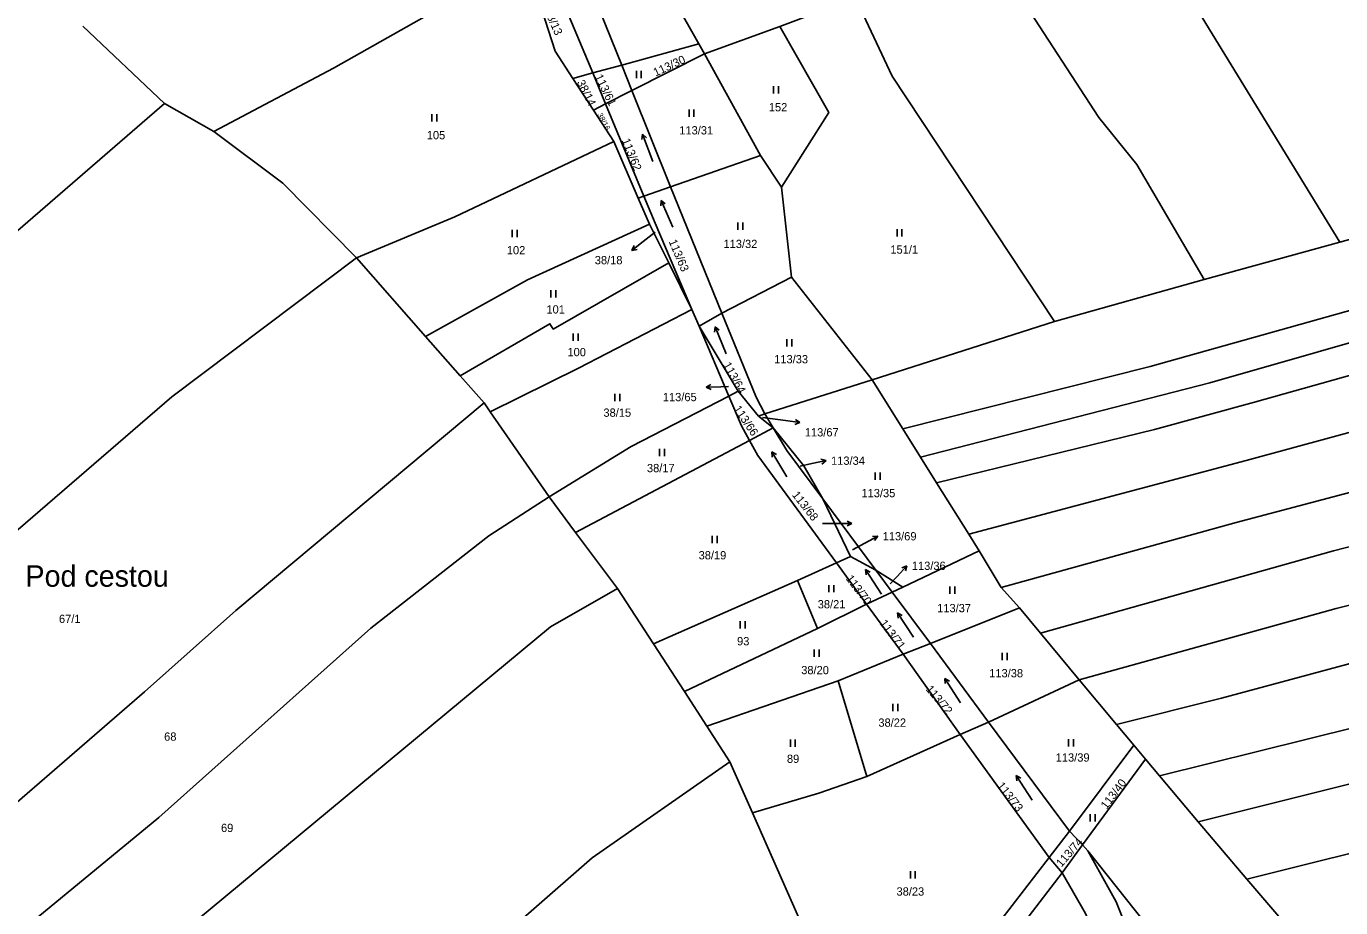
# Model space of a CAD drawing. Extents: x -751333 to -746055, y -1133395 to -1129777.
# Drawn here: x -747546.5 to -747276.5, y -1131322.6 to -1131141.4 of the extents above; entities that cross this region are included whole.
import ezdxf

# ---------------------------------------------------------------- set-up
doc = ezdxf.new("R2010")
doc.units = 0
for name, color, linetype in [('Hranice parcel', 7, 'Continuous'), ('Parcelní čísla', 7, 'Continuous'), ('Pop  PČ popisy', 7, 'Continuous'), ('Značky kultur', 7, 'Continuous')]:
    doc.layers.add(name, color=color, linetype=linetype)

msp = doc.modelspace()

# ---------------------------------------------------------------- linework, layer by layer
at = {"layer": 'Hranice parcel'}
for p, q in [((-747408.38, -1131145.07), (-747431.95, -1131103.02)), ((-747440.84, -1131108.03), (-747424.22, -1131149.41)), ((-747430.18, -1131151.04), (-747446.81, -1131111.05)), ((-747376.22, -1131135.6), (-747391.74, -1131141.48)), ((-747518.15, -1131157.34), (-747534.94, -1131141.41)), ((-747407.22, -1131147.14), (-747391.74, -1131141.48)), ((-747424.22, -1131149.41), (-747408.38, -1131145.07)), ((-747407.22, -1131147.14), (-747408.38, -1131145.07)), ((-747422.11, -1131154.66), (-747407.22, -1131147.14)), ((-747395.7, -1131168), (-747407.22, -1131147.14)), ((-747430.18, -1131151.04), (-747424.22, -1131149.41)), ((-747424.22, -1131149.41), (-747422.11, -1131154.66)), ((-747434.26, -1131152.16), (-747430.18, -1131151.04)), ((-747434.26, -1131152.16), (-747430.03, -1131158.67)), ((-747427.53, -1131157.41), (-747430.18, -1131151.04)), ((-747427.53, -1131157.41), (-747422.11, -1131154.66)), ((-747422.11, -1131154.66), (-747414.16, -1131174.44)), ((-747508, -1131163.09), (-747518.15, -1131157.34)), ((-747430.03, -1131158.67), (-747427.53, -1131157.41)), ((-747430.03, -1131158.67), (-747425.84, -1131165.11)), ((-747419.66, -1131176.34), (-747427.53, -1131157.41)), ((-747425.84, -1131165.11), (-747420.83, -1131176.75)), ((-747414.16, -1131174.44), (-747395.7, -1131168)), ((-747391.42, -1131174.47), (-747395.7, -1131168)), ((-747419.66, -1131176.34), (-747414.16, -1131174.44)), ((-747414.16, -1131174.44), (-747403.63, -1131200.37)), ((-747389.33, -1131193.02), (-747391.42, -1131174.47)), ((-747420.83, -1131176.75), (-747419.66, -1131176.34)), ((-747420.83, -1131176.75), (-747418.53, -1131182.09)), ((-747418.53, -1131182.09), (-747414.55, -1131190.08)), ((-747304.55, -1131193.5), (-747276.68, -1131185.78)), ((-747464.5, -1131205.17), (-747478.68, -1131189)), ((-747414.55, -1131190.08), (-747409.79, -1131199.63)), ((-747403.63, -1131200.37), (-747389.33, -1131193.02)), ((-747372.79, -1131214.07), (-747389.33, -1131193.02)), ((-747335.3, -1131202.07), (-747304.55, -1131193.5)), ((-747408.32, -1131203.08), (-747409.79, -1131199.63)), ((-747408.32, -1131203.08), (-747403.63, -1131200.37)), ((-747372.79, -1131214.07), (-747335.3, -1131202.07)), ((-747402.18, -1131217.46), (-747408.32, -1131203.08)), ((-747408.32, -1131203.08), (-747400.3, -1131216.43)), ((-747457.41, -1131213.25), (-747464.5, -1131205.17)), ((-747452.5, -1131218.84), (-747457.41, -1131213.25)), ((-747394.81, -1131221.1), (-747372.79, -1131214.07)), ((-747366.49, -1131224.14), (-747372.79, -1131214.07)), ((-747402.18, -1131217.46), (-747400.3, -1131216.43)), ((-747400.3, -1131216.43), (-747396.13, -1131221.54)), ((-747451.24, -1131220.66), (-747452.5, -1131218.84)), ((-747451.24, -1131220.66), (-747439.12, -1131238.12)), ((-747396.13, -1131221.54), (-747394.81, -1131221.1)), ((-747393.08, -1131223.94), (-747396.13, -1131221.54)), ((-747394.81, -1131221.1), (-747393.08, -1131223.94)), ((-747397.95, -1131226.54), (-747393.08, -1131223.94)), ((-747362.83, -1131229.98), (-747366.49, -1131224.14)), ((-747359.55, -1131235.22), (-747362.83, -1131229.98)), ((-747352.93, -1131245.79), (-747359.55, -1131235.22)), ((-747439.12, -1131238.12), (-747433.68, -1131245.43)), ((-747377.23, -1131250.36), (-747382.92, -1131238.52)), ((-747382.92, -1131238.52), (-747372.02, -1131253.19)), ((-747433.68, -1131245.43), (-747425.11, -1131256.95)), ((-747350.79, -1131249.21), (-747352.93, -1131245.79)), ((-747380.11, -1131251.72), (-747377.23, -1131250.36)), ((-747377.23, -1131250.36), (-747372.02, -1131253.19)), ((-747366.48, -1131256.66), (-747350.79, -1131249.21)), ((-747346.25, -1131256.73), (-747350.79, -1131249.21)), ((-747388.07, -1131255.34), (-747380.11, -1131251.72)), ((-747373.91, -1131260.21), (-747380.11, -1131251.72)), ((-747372.02, -1131253.19), (-747366.48, -1131256.66)), ((-747372.02, -1131253.19), (-747368.67, -1131257.7)), ((-747417.7, -1131268.35), (-747388.07, -1131255.34)), ((-747388.07, -1131255.34), (-747384.01, -1131265.18)), ((-747425.11, -1131256.95), (-747417.7, -1131268.35)), ((-747373.91, -1131260.21), (-747368.67, -1131257.7)), ((-747368.67, -1131257.7), (-747366.48, -1131256.66)), ((-747368.67, -1131257.7), (-747360.8, -1131268.29)), ((-747342.53, -1131260.96), (-747346.25, -1131256.73)), ((-747373.91, -1131260.21), (-747384.01, -1131265.18)), ((-747366.42, -1131270.45), (-747373.91, -1131260.21)), ((-747360.8, -1131268.29), (-747342.53, -1131260.96)), ((-747338.19, -1131266.17), (-747342.53, -1131260.96)), ((-747384.01, -1131265.18), (-747411.33, -1131278.16)), ((-747330.24, -1131275.71), (-747338.19, -1131266.17)), ((-747411.33, -1131278.16), (-747417.7, -1131268.35)), ((-747366.42, -1131270.45), (-747360.8, -1131268.29)), ((-747360.8, -1131268.29), (-747348.89, -1131284.46)), ((-747379.74, -1131275.95), (-747366.42, -1131270.45)), ((-747354.67, -1131286.99), (-747366.42, -1131270.45)), ((-747406.7, -1131285.28), (-747379.74, -1131275.95)), ((-747379.74, -1131275.95), (-747373.86, -1131295.58)), ((-747348.89, -1131284.46), (-747330.24, -1131275.71)), ((-747322.57, -1131284.9), (-747330.24, -1131275.71)), ((-747411.33, -1131278.16), (-747406.7, -1131285.28)), ((-747401.97, -1131292.55), (-747406.7, -1131285.28)), ((-747354.67, -1131286.99), (-747348.89, -1131284.46)), ((-747348.89, -1131284.46), (-747332.21, -1131306.86)), ((-747319.02, -1131289.16), (-747322.57, -1131284.9)), ((-747373.86, -1131295.58), (-747354.67, -1131286.99)), ((-747336.38, -1131312.26), (-747354.67, -1131286.99)), ((-747332.21, -1131306.86), (-747319.02, -1131289.16)), ((-747316.65, -1131292.01), (-747319.02, -1131289.16)), ((-747397.34, -1131303.04), (-747401.97, -1131292.55)), ((-747316.65, -1131292.01), (-747329.56, -1131309.63)), ((-747313.75, -1131295.48), (-747316.65, -1131292.01)), ((-747305.83, -1131304.88), (-747313.75, -1131295.48)), ((-747397.34, -1131303.04), (-747384.78, -1131331.55)), ((-747336.38, -1131312.26), (-747332.21, -1131306.86)), ((-747332.21, -1131306.86), (-747329.56, -1131309.63)), ((-747295.77, -1131316.67), (-747305.83, -1131304.88)), ((-747329.56, -1131309.63), (-747333.76, -1131315.41)), ((-747328.48, -1131310.88), (-747329.56, -1131309.63)), ((-747370.27, -1131355.92), (-747336.38, -1131312.26)), ((-747333.76, -1131315.41), (-747336.38, -1131312.26)), ((-747286.32, -1131327.71), (-747295.77, -1131316.67))]:
    msp.add_line(p, q, dxfattribs=at)
for points in [[(-747455.08, -1130941.09), (-747407, -1130998.24), (-747346.3, -1131076.82), (-747308.86, -1131133.19), (-747276.68, -1131185.78)], [(-747466.65, -1130957.41), (-747426.05, -1131003.14), (-747390.52, -1131051.98), (-747379.77, -1131069.99), (-747357.62, -1131107.84), (-747342.16, -1131135.57), (-747326.23, -1131160.19), (-747318.42, -1131169.83), (-747304.55, -1131193.5)], [(-747444.14, -1131128.36), (-747441.29, -1131135.89), (-747437.88, -1131146.58), (-747434.26, -1131152.16)], [(-747376.22, -1131135.6), (-747368.67, -1131151.69), (-747335.3, -1131202.07)], [(-747464.26, -1131139.24), (-747483.41, -1131150.03), (-747508, -1131163.09)], [(-747366.49, -1131224.14), (-747315.64, -1131211.37), (-747239.01, -1131189.85), (-747208.02, -1131183.24), (-747142.94, -1131169.86), (-747059.23, -1131151.85), (-746994.26, -1131139.92)], [(-747391.74, -1131141.48), (-747381.7, -1131159.18), (-747391.42, -1131174.47)], [(-747362.83, -1131229.98), (-747303.37, -1131214.71), (-747236.14, -1131195.43), (-747183.65, -1131184.91), (-747140.79, -1131175.19), (-747094.5, -1131166.43), (-747035.79, -1131154.71), (-746990.07, -1131145.5)], [(-747359.55, -1131235.22), (-747314.76, -1131224.28), (-747294.21, -1131218.7), (-747239.88, -1131203.41), (-747217.65, -1131198.22), (-747179.1, -1131189.54), (-747110.35, -1131174.95), (-747094.58, -1131172.24), (-747057.06, -1131164.91), (-746987.65, -1131152.16)], [(-747637.6, -1131258.56), (-747605.36, -1131233.4), (-747586.04, -1131216.89), (-747564.17, -1131197.09), (-747518.15, -1131157.34)], [(-747478.68, -1131189), (-747493.84, -1131173.69), (-747508, -1131163.09)], [(-747352.93, -1131245.79), (-747295.96, -1131230.66), (-747233.75, -1131213.76), (-747157.12, -1131196.99), (-747060.9, -1131176.27), (-747030, -1131171.43), (-746983.59, -1131163.34)], [(-747425.84, -1131165.11), (-747458.47, -1131180.59), (-747478.68, -1131189)], [(-747409.79, -1131199.63), (-747417.35, -1131181.9), (-747419.66, -1131176.34)], [(-747346.25, -1131256.73), (-747297.98, -1131243.4), (-747234.57, -1131226.59), (-747209.63, -1131221.41), (-747174.99, -1131213.76), (-747135.39, -1131204.28), (-747094.05, -1131195.6), (-747052.94, -1131188.25), (-746980.29, -1131175.39)], [(-747276.68, -1131185.78), (-747264.57, -1131182.48), (-747243.06, -1131175.98)], [(-747418.53, -1131182.09), (-747443.59, -1131193.55), (-747464.5, -1131205.17)], [(-747338.19, -1131266.17), (-747277.98, -1131249.2), (-747235.43, -1131238.28), (-747213.21, -1131234.14), (-747187.16, -1131228.96), (-747140.48, -1131218.28), (-747086.15, -1131207.37), (-747047.59, -1131199.64), (-746976.21, -1131185.45)], [(-747478.68, -1131189), (-747516.61, -1131217.55), (-747562.75, -1131257.36), (-747584.62, -1131275.69), (-747613.72, -1131296.16)], [(-747414.55, -1131190.08), (-747438.27, -1131203.66), (-747438.96, -1131202.58), (-747457.41, -1131213.25)], [(-747330.24, -1131275.71), (-747277.42, -1131261.08), (-747228.35, -1131248.89), (-747189.96, -1131241.4), (-747149.33, -1131232.63), (-747125.6, -1131227.7), (-747062.34, -1131215.02), (-746993.98, -1131202.44), (-746969.25, -1131197.46)], [(-747409.79, -1131199.63), (-747433.07, -1131211.69), (-747451.24, -1131220.66)], [(-747403.63, -1131200.37), (-747396.62, -1131217.65), (-747394.81, -1131221.1)], [(-747322.57, -1131284.9), (-747301.01, -1131279.52), (-747228.28, -1131259.93), (-747190.83, -1131253.47), (-747160.64, -1131247.09), (-747111.02, -1131236.65), (-747064.81, -1131227), (-747042.19, -1131222.79), (-746964.73, -1131206.9)], [(-747439.12, -1131238.12), (-747422.3, -1131227.8), (-747402.18, -1131217.46)], [(-747397.95, -1131226.54), (-747399.59, -1131223.53), (-747402.18, -1131217.46)], [(-747587.97, -1131330.74), (-747567.99, -1131317.8), (-747522.26, -1131278.21), (-747503.48, -1131261.46), (-747452.5, -1131218.84)], [(-747313.75, -1131295.48), (-747253.05, -1131280.4), (-747231.07, -1131274.58), (-747201.09, -1131268.16), (-747174.02, -1131263.18), (-747155.54, -1131259.35), (-747082.77, -1131244.23), (-747040.5, -1131235.77), (-746958.82, -1131219.23)], [(-747393.08, -1131223.94), (-747390.29, -1131228.61), (-747382.92, -1131238.52)], [(-747382.92, -1131238.52), (-747386.77, -1131231.73), (-747393.08, -1131223.94)], [(-747433.68, -1131245.43), (-747412.33, -1131234.19), (-747397.95, -1131226.54)], [(-747380.11, -1131251.72), (-747396.26, -1131229.64), (-747397.95, -1131226.54)], [(-747305.83, -1131304.88), (-747229.31, -1131285.82), (-747172.59, -1131275.8), (-747161.6, -1131273.01), (-747136.9, -1131266.58), (-747124.63, -1131263.55), (-747104.54, -1131259.94), (-747060.99, -1131251.11), (-747007.85, -1131241), (-746953.9, -1131229.5)], [(-747573.75, -1131348.78), (-747519.29, -1131304), (-747475.75, -1131265.13), (-747451.48, -1131246.17), (-747439.12, -1131238.12)], [(-747295.77, -1131316.67), (-747260.4, -1131307.82), (-747220.48, -1131297.78), (-747153.89, -1131284.38), (-747109.03, -1131274.27), (-747084.89, -1131269.09), (-747048.4, -1131261.6), (-746996.46, -1131251.25), (-746948.48, -1131240.82)], [(-747560.74, -1131366.12), (-747532.83, -1131342.86), (-747438.82, -1131264.87), (-747425.11, -1131256.95)], [(-747534.26, -1131400.17), (-747480.38, -1131356.14), (-747430.3, -1131312.29), (-747401.97, -1131292.55)], [(-747373.86, -1131295.58), (-747383.75, -1131299), (-747397.34, -1131303.04)], [(-747281.5, -1131480.62), (-747293.52, -1131448.9), (-747294.79, -1131442.89), (-747294.49, -1131425.32), (-747301.04, -1131375.44), (-747322.63, -1131321.35), (-747328.48, -1131310.88)], [(-747281.5, -1131480.62), (-747268.38, -1131439.1), (-747266.03, -1131410.81), (-747274.76, -1131385.48), (-747283.22, -1131370.63), (-747296.93, -1131350.55), (-747328.48, -1131310.88)], [(-747333.76, -1131315.41), (-747364.89, -1131355.97), (-747369.3, -1131361.68), (-747376.46, -1131367.68)], [(-747333.76, -1131315.41), (-747328.97, -1131323.74), (-747306.78, -1131376.04), (-747305.04, -1131391.08)]]:
    msp.add_lwpolyline(points, dxfattribs=at)
at = {"layer": 'Pop  PČ popisy'}
for p, q in [((-747419.78, -1131185.67), (-747422.145, -1131187.518)), ((-747417.31, -1131183.76), (-747419.78, -1131185.67)), ((-747422.145, -1131187.518), (-747421.664, -1131186.506)), ((-747422.145, -1131187.518), (-747421.047, -1131187.296)), ((-747406.869, -1131215.615), (-747405.886, -1131215.079)), ((-747403.87, -1131215.51), (-747406.869, -1131215.615)), ((-747406.869, -1131215.615), (-747405.851, -1131216.08)), ((-747402.28, -1131215.44), (-747403.87, -1131215.51)), ((-747395.32, -1131221.83), (-747390.57, -1131222.47)), ((-747390.57, -1131222.47), (-747387.598, -1131222.888)), ((-747387.598, -1131222.888), (-747388.66, -1131223.244)), ((-747387.598, -1131222.888), (-747388.52, -1131222.252)), ((-747387.54, -1131231.81), (-747385.15, -1131231.31)), ((-747385.15, -1131231.31), (-747382.215, -1131230.686)), ((-747382.215, -1131230.686), (-747383.298, -1131230.404)), ((-747382.215, -1131230.686), (-747383.09, -1131231.384)), ((-747376.82, -1131248.99), (-747374.26, -1131247.63)), ((-747374.26, -1131247.63), (-747371.61, -1131246.221)), ((-747371.61, -1131246.221), (-747372.73, -1131246.249)), ((-747371.61, -1131246.221), (-747372.259, -1131247.133)), ((-747367.66, -1131254.49), (-747365.613, -1131252.295)), ((-747365.613, -1131252.295), (-747366.663, -1131252.686)), ((-747365.613, -1131252.295), (-747365.93, -1131253.369)), ((-747369.1, -1131256.04), (-747367.66, -1131254.49))]:
    msp.add_line(p, q, dxfattribs=at)
at = {"layer": 'Značky kultur'}
for p, q in [((-747421.191, -1131152.09), (-747421.191, -1131150.59)), ((-747420.19, -1131152.09), (-747420.19, -1131150.59)), ((-747393.011, -1131155.26), (-747393.011, -1131153.76)), ((-747392.01, -1131155.26), (-747392.01, -1131153.76)), ((-747410.371, -1131160.06), (-747410.371, -1131158.56)), ((-747409.37, -1131160.06), (-747409.37, -1131158.56)), ((-747463.191, -1131160.99), (-747463.191, -1131159.49)), ((-747462.19, -1131160.99), (-747462.19, -1131159.49)), ((-747419.953, -1131163.62), (-747420.071, -1131164.712)), ((-747417.803, -1131169.222), (-747419.953, -1131163.62)), ((-747419.953, -1131163.62), (-747419.135, -1131164.353)), ((-747416.119, -1131177.27), (-747416.18, -1131178.367)), ((-747413.679, -1131182.751), (-747416.119, -1131177.27)), ((-747416.119, -1131177.27), (-747415.264, -1131177.959)), ((-747400.351, -1131183.28), (-747400.351, -1131181.78)), ((-747399.35, -1131183.28), (-747399.35, -1131181.78)), ((-747367.651, -1131184.63), (-747367.651, -1131183.13)), ((-747366.65, -1131184.63), (-747366.65, -1131183.13)), ((-747446.721, -1131184.75), (-747446.721, -1131183.25)), ((-747445.72, -1131184.75), (-747445.72, -1131183.25)), ((-747438.741, -1131197.17), (-747438.741, -1131195.67)), ((-747437.74, -1131197.17), (-747437.74, -1131195.67)), ((-747434.171, -1131206.06), (-747434.171, -1131204.56)), ((-747433.17, -1131206.06), (-747433.17, -1131204.56)), ((-747405.022, -1131203.199), (-747405.121, -1131204.293)), ((-747402.775, -1131208.762), (-747405.022, -1131203.199)), ((-747405.022, -1131203.199), (-747404.191, -1131203.918)), ((-747390.281, -1131207.21), (-747390.281, -1131205.71)), ((-747389.28, -1131207.21), (-747389.28, -1131205.71)), ((-747425.631, -1131218.5), (-747425.631, -1131217)), ((-747424.63, -1131218.5), (-747424.63, -1131217)), ((-747416.421, -1131229.77), (-747416.421, -1131228.27)), ((-747415.42, -1131229.77), (-747415.42, -1131228.27)), ((-747390.266, -1131234.002), (-747393.357, -1131228.859)), ((-747393.357, -1131228.859), (-747393.283, -1131229.955)), ((-747393.357, -1131228.859), (-747392.424, -1131229.439)), ((-747372.151, -1131234.66), (-747372.151, -1131233.16)), ((-747371.15, -1131234.66), (-747371.15, -1131233.16)), ((-747382.943, -1131243.609), (-747376.943, -1131243.609)), ((-747376.943, -1131243.609), (-747377.92, -1131243.107)), ((-747376.943, -1131243.609), (-747377.92, -1131244.11)), ((-747405.621, -1131247.67), (-747405.621, -1131246.17)), ((-747404.62, -1131247.67), (-747404.62, -1131246.17)), ((-747370.838, -1131258.097), (-747374.106, -1131253.065)), ((-747374.106, -1131253.065), (-747373.994, -1131254.158)), ((-747374.106, -1131253.065), (-747373.153, -1131253.611)), ((-747381.661, -1131257.75), (-747381.661, -1131256.25)), ((-747380.66, -1131257.75), (-747380.66, -1131256.25)), ((-747356.811, -1131258.04), (-747356.811, -1131256.54)), ((-747355.81, -1131258.04), (-747355.81, -1131256.54)), ((-747399.861, -1131265.2), (-747399.861, -1131263.7)), ((-747398.86, -1131265.2), (-747398.86, -1131263.7)), ((-747364.278, -1131266.977), (-747367.546, -1131261.945)), ((-747367.546, -1131261.945), (-747367.434, -1131263.038)), ((-747367.546, -1131261.945), (-747366.593, -1131262.491)), ((-747384.651, -1131271.02), (-747384.651, -1131269.52)), ((-747383.65, -1131271.02), (-747383.65, -1131269.52)), ((-747346.061, -1131271.67), (-747346.061, -1131270.17)), ((-747345.06, -1131271.67), (-747345.06, -1131270.17)), ((-747354.598, -1131280.457), (-747357.866, -1131275.425)), ((-747357.866, -1131275.425), (-747357.754, -1131276.518)), ((-747357.866, -1131275.425), (-747356.913, -1131275.971)), ((-747368.521, -1131282.18), (-747368.521, -1131280.68)), ((-747367.52, -1131282.18), (-747367.52, -1131280.68)), ((-747389.551, -1131289.49), (-747389.551, -1131287.99)), ((-747388.55, -1131289.49), (-747388.55, -1131287.99)), ((-747332.421, -1131289.43), (-747332.421, -1131287.93)), ((-747331.42, -1131289.43), (-747331.42, -1131287.93)), ((-747339.898, -1131300.437), (-747343.166, -1131295.405)), ((-747343.166, -1131295.405), (-747343.054, -1131296.498)), ((-747343.166, -1131295.405), (-747342.213, -1131295.951)), ((-747327.981, -1131304.85), (-747327.981, -1131303.35)), ((-747326.98, -1131304.85), (-747326.98, -1131303.35)), ((-747364.901, -1131316.52), (-747364.901, -1131315.02)), ((-747363.9, -1131316.52), (-747363.9, -1131315.02))]:
    msp.add_line(p, q, dxfattribs=at)

# ---------------------------------------------------------------- texts
at = {"layer": 'Parcelní čísla'}
for s, height, rotation, p in [('38/13', 1.7, 294, (-747440.146, -1131138.275)), ('113/30', 1.7, 25, (-747417.25, -1131151.8)), ('38/14', 1.7, 297, (-747433.497, -1131152.965)), ('113/61', 1.7, 296, (-747429.793, -1131151.772)), ('38/16', 1.14, 298, (-747429.273, -1131159.597)), ('113/62', 1.7, 292, (-747424.228, -1131164.868)), ('113/63', 1.7, 293, (-747414.602, -1131185.652)), ('113/64', 1.7, 299, (-747403.453, -1131210.992)), ('113/66', 1.7, 304, (-747401.334, -1131220.045)), ('113/68', 1.7, 308, (-747389.309, -1131237.773)), ('113/70', 1.7, 307, (-747378.258, -1131254.961)), ('113/71', 1.7, 307, (-747371.318, -1131264.141)), ('113/72', 1.7, 310, (-747361.861, -1131277.706)), ('113/40', 1.7, 53, (-747324.611, -1131302.461)), ('113/73', 1.7, 308, (-747347.219, -1131297.523)), ('113/74', 1.7, 49, (-747333.888, -1131314.337))]:
    msp.add_text(s, height=height, rotation=rotation, dxfattribs=at).set_placement(p)
for s, p in [('152', (-747394, -1131158.92)), ('105', (-747464.26, -1131164.66)), ('113/31', (-747412.39, -1131163.67)), ('113/32', (-747403.31, -1131187.01)), ('102', (-747447.82, -1131188.3)), ('38/18', (-747429.747, -1131190.348)), ('151/1', (-747369.02, -1131188.17)), ('101', (-747439.68, -1131200.47)), ('100', (-747435.36, -1131209.24)), ('113/33', (-747392.89, -1131210.7)), ('113/65', (-747415.765, -1131218.478)), ('38/15', (-747427.97, -1131221.68)), ('113/67', (-747386.6, -1131225.718)), ('38/17', (-747419.03, -1131233.07)), ('113/34', (-747381.21, -1131231.55)), ('113/35', (-747374.96, -1131238.21)), ('113/69', (-747370.61, -1131247.08)), ('38/19', (-747408.42, -1131250.98)), ('113/36', (-747364.61, -1131253.15)), ('38/21', (-747383.95, -1131261.05)), ('113/37', (-747359.41, -1131261.84)), ('67/1', (-747539.82, -1131264.06)), ('93', (-747400.52, -1131268.64)), ('38/20', (-747387.34, -1131274.58)), ('113/38', (-747348.72, -1131275.22)), ('38/22', (-747371.49, -1131285.37)), ('68', (-747518.21, -1131288.24)), ('89', (-747390.27, -1131292.8)), ('113/39', (-747335.06, -1131292.54)), ('69', (-747506.53, -1131307)), ('38/23', (-747367.76, -1131320.07))]:
    msp.add_text(s, height=1.7, dxfattribs=at).set_placement(p)
at = {"layer": 'Pop  PČ popisy'}
msp.add_text('Pod cestou', height=4.4, dxfattribs=at).set_placement((-747546.696, -1131256.6))

doc.saveas('drawing.dxf')
